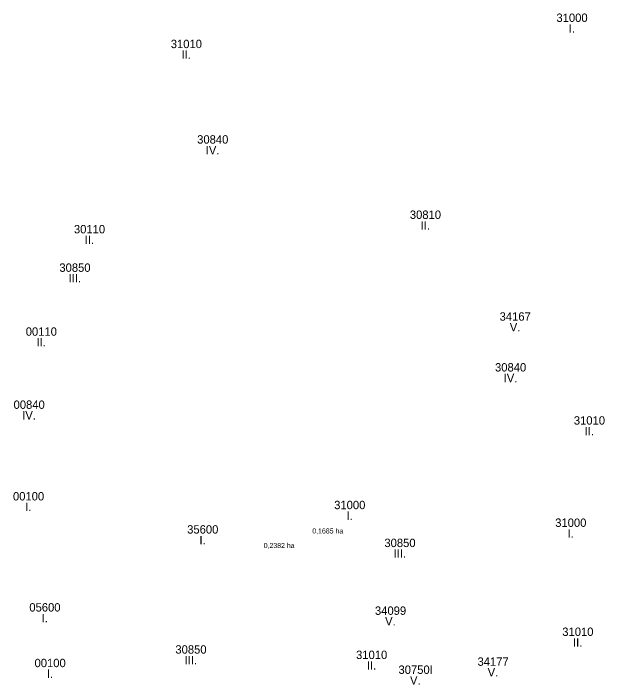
# Model space of a CAD drawing. Extents: x -555004 to -553595, y -1185878 to -1184279.
import ezdxf

# ---------------------------------------------------------------- set-up
doc = ezdxf.new("R2010")
doc.units = 0
doc.layers.add('BPEJ', color=7, linetype='Continuous')
doc.layers.add('ZPF_zabor', color=7, linetype='Continuous')

msp = doc.modelspace()

# ---------------------------------------------------------------- texts
at = {"layer": 'BPEJ'}
for s, p in [('31000', (-553709.5, -1184298.8)), ('I.', (-553680.2, -1184324.3)), ('31010', (-554629, -1184361.2)), ('II.', (-554603.3, -1184386.7)), ('30840', (-554566.1, -1184588.8)), ('IV.', (-554545.6, -1184614.3)), ('30810', (-554059, -1184768.2)), ('30110', (-554859.9, -1184802.7)), ('II.', (-554033.3, -1184793.7)), ('II.', (-554834.2, -1184828.2)), ('30850', (-554894.6, -1184894.3)), ('III.', (-554872.6, -1184919.7)), ('34167', (-553845, -1185010.8)), ('V.', (-553820.7, -1185036.3)), ('00110', (-554974.8, -1185046.7)), ('II.', (-554949.2, -1185072.1)), ('30840', (-553855.9, -1185131.9)), ('IV.', (-553835.3, -1185157.4)), ('00840', (-555003.8, -1185220.9)), ('IV.', (-554983.2, -1185246.4)), ('31010', (-553668, -1185258.5)), ('II.', (-553642.4, -1185283.9)), ('00100', (-555005.2, -1185439.2)), ('31000', (-554239.4, -1185460)), ('I.', (-554975.9, -1185464.6)), ('I.', (-554210.1, -1185485.5)), ('31000', (-553712.4, -1185502.2)), ('35600', (-554589.9, -1185518.2)), ('I.', (-553683.1, -1185527.7)), ('I.', (-554560.6, -1185543.6)), ('30850', (-554119.7, -1185550.3)), ('III.', (-554097.7, -1185575.8)), ('05600', (-554966.2, -1185704)), ('34099', (-554142.2, -1185711.8)), ('I.', (-554936.9, -1185729.4)), ('V.', (-554118, -1185737.2)), ('31010', (-553695.6, -1185762.1)), ('II.', (-553670, -1185787.5)), ('30850', (-554618, -1185804.3)), ('31010', (-554187.2, -1185817.1)), ('00100', (-554953.8, -1185836.5)), ('III.', (-554596, -1185829.7)), ('II.', (-554161.5, -1185842.6)), ('34177', (-553897.7, -1185833.2)), ('30750I', (-554086.1, -1185852.5)), ('V.', (-553873.5, -1185858.7)), ('I.', (-554924.5, -1185862)), ('V.', (-554058.6, -1185878))]:
    msp.add_text(s, height=20, dxfattribs=at).set_placement(p)
at = {"layer": 'ZPF_zabor'}
for s, p in [('0,1685 ha', (-554291.6, -1185517.9)), ('0,2382 ha', (-554407.5, -1185552.6))]:
    msp.add_text(s, height=12, dxfattribs=at).set_placement(p)

doc.saveas('drawing.dxf')
